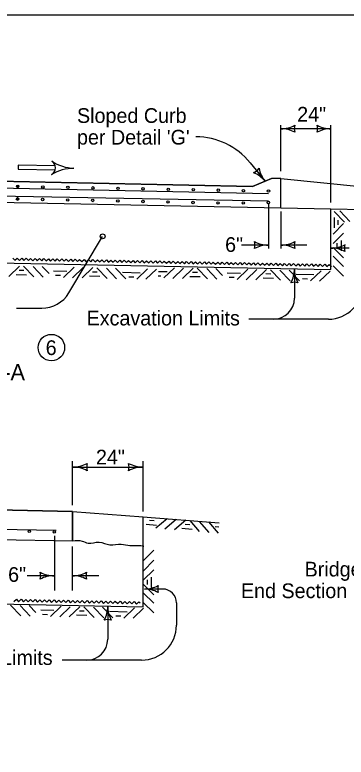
# Model space of a CAD drawing. Extents: x 8925 to 81668, y 4369 to 11918.
# Drawn here: x 17971 to 18420, y 8936 to 9944 of the extents above; entities that cross this region are included whole.
import ezdxf

# ---------------------------------------------------------------- set-up
doc = ezdxf.new("R2010")
doc.units = 0
for name, color, linetype in [('dsnShtPlotShapeBatchPrint', 7, 'Continuous'), ('dsnStdBorder', 7, 'Continuous'), ('SheetBorder', 7, 'Continuous')]:
    doc.layers.add(name, color=color, linetype=linetype)

msp = doc.modelspace()

# ---------------------------------------------------------------- linework, layer by layer
at = {"layer": 'dsnShtPlotShapeBatchPrint'}
msp.add_line((18314.8, 9691.1), (17583.2, 9704.6), dxfattribs=at)
at = {"layer": 'dsnStdBorder'}
for p, q in [((18331.8, 9731.9), (18331.8, 9794)), ((18399.8, 9689), (18399.8, 9794)), ((18399.8, 9789.3), (18331.8, 9789.3)), ((18290.1, 9743.1), (18310.3, 9717.9)), ((18025.3, 9733.3), (18025.3, 9733.3)), ((18025.4, 9739.1), (18025.4, 9739.1)), ((18293.5, 9710.9), (17583.3, 9725.2)), ((17583.3, 9725.2), (18293.5, 9710.9)), ((18319, 9721.5), (18293.5, 9710.9)), ((18293.5, 9710.9), (18319, 9721.5)), ((18331.8, 9721.5), (18319, 9721.5)), ((18331.8, 9721.5), (18319, 9721.5)), ((18331.8, 9681.8), (18331.8, 9721.5)), ((18331.8, 9681.8), (18331.8, 9721.5)), ((18331.8, 9721.5), (18444.1, 9710.3)), ((17583.3, 9716.2), (18315, 9701.5)), ((17582.7, 9696.8), (18331.8, 9681.8)), ((17583.8, 9696.8), (18331.8, 9681.8)), ((18314.8, 9687.3), (18314.8, 9626.6)), ((18331.8, 9681.8), (18399.8, 9680.4)), ((18399.8, 9598), (18399.8, 9680.4)), ((18399.8, 9680.4), (18577.7, 9676.8)), ((18331.8, 9677.1), (18331.8, 9626.6)), ((18404.3, 9676.9), (18418.2, 9662.5)), ((18411.6, 9677.9), (18425.4, 9663.4)), ((18402.9, 9646.3), (18417, 9660.5)), ((18043.9, 9566.2), (18089.9, 9643.1)), ((18402.7, 9633.3), (18416.8, 9647.4)), ((18314.8, 9631.3), (18278.2, 9631.3)), ((18367, 9631.3), (18331.8, 9631.3)), ((18424.6, 9627.2), (18399.8, 9627.2)), ((18402.7, 9627.9), (18416.8, 9613.8)), ((17583.3, 9614.4), (18399.8, 9598)), ((18402.7, 9616.3), (18416.8, 9602.2)), ((17977.1, 9602.6), (17962.7, 9588.7)), ((17982.5, 9602.5), (17996.4, 9588)), ((17995.5, 9602), (18009.4, 9587.6)), ((18008, 9602), (18017.1, 9592.5)), ((18051.2, 9601.1), (18036.8, 9587.2)), ((18063.6, 9600.6), (18049.2, 9586.8)), ((18076.6, 9600.6), (18062.2, 9586.7)), ((18082, 9600.5), (18095.9, 9586)), ((18095, 9600), (18108.9, 9585.6)), ((18107.5, 9600), (18121.4, 9585.5)), ((18187.2, 9600.4), (18172.8, 9586.6)), ((18199.7, 9600), (18185.3, 9586.1)), ((18212.7, 9599.9), (18198.3, 9586.1)), ((18218.1, 9599.8), (18232, 9585.4)), ((18231.1, 9599.3), (18245, 9584.9)), ((18243.6, 9599.3), (18252.7, 9589.8)), ((18402.7, 9603.3), (18416.8, 9589.1)), ((18150.7, 9599.1), (18136.3, 9585.2)), ((18163.2, 9598.6), (18148.7, 9584.8)), ((18286.8, 9598.5), (18272.4, 9584.6)), ((18299.2, 9598), (18284.8, 9584.1)), ((18312.2, 9597.9), (18297.8, 9584.1)), ((18317.6, 9597.8), (18331.5, 9583.4)), ((18330.6, 9597.3), (18344.5, 9582.9)), ((18343.1, 9597.3), (18357, 9582.9)), ((18350.2, 9599), (18350.2, 9559)), ((18386.3, 9596.5), (18371.9, 9582.6)), ((18398.8, 9596), (18384.3, 9582.1)), ((17973.1, 9545.5), (18007.4, 9545.5)), ((18396.2, 9530.6), (18288.4, 9530.6)), ((18049.1, 9278.1), (18049.1, 9337.8)), ((18145.1, 9269.5), (18145.1, 9337.8)), ((18049.1, 9329.8), (18145.1, 9329.8)), ((18049.1, 9269.5), (17676.1, 9277)), ((17676.1, 9277), (18049.1, 9269.5)), ((18049.1, 9229.5), (18049.1, 9269.5)), ((18049.1, 9269.5), (18049.1, 9229.5)), ((18049.1, 9269.5), (18145.1, 9262.1)), ((18144.4, 9262.1), (18247.9, 9254.1)), ((18145.1, 9139.8), (18145.1, 9262.1)), ((18177.3, 9259.6), (18162.1, 9246.6)), ((18189.7, 9258.4), (18174.5, 9245.4)), ((18202.7, 9257.6), (18187.5, 9244.6)), ((18208.1, 9257.2), (18221.1, 9242)), ((18027, 9243.5), (17725.6, 9249.6)), ((18221.1, 9256), (18234.1, 9240.8)), ((18233.5, 9255.3), (18246.5, 9240.1)), ((17676.1, 9237), (18049.1, 9229.5)), ((17676.1, 9237), (18049.1, 9229.5)), ((18025.1, 9162), (18025.1, 9236.4)), ((18049.1, 9162), (18049.1, 9221.7)), ((18145.3, 9202.7), (18159.4, 9216.9)), ((18145.3, 9188.9), (18159.4, 9203.1)), ((18145.1, 9175.9), (18159.2, 9190.1)), ((18024.1, 9182.1), (17987.5, 9182.1)), ((18084.8, 9182.1), (18049.1, 9182.1)), ((18145.1, 9170.5), (18159.2, 9156.4)), ((18145.1, 9158.9), (18159.2, 9144.8)), ((18171.2, 9164.1), (18146.5, 9164.1)), ((17676.1, 9149.2), (18145, 9139.8)), ((18145.1, 9145.9), (18159.2, 9131.7)), ((17964.9, 9142), (17978.7, 9127.5)), ((17977.9, 9141.5), (17991.7, 9127.1)), ((17990.3, 9141.5), (17999.4, 9132)), ((18033.5, 9140.6), (18019.1, 9126.7)), ((18046, 9140.1), (18031.6, 9126.3)), ((18059, 9140.1), (18044.6, 9126.2)), ((18064.4, 9140), (18078.3, 9125.5)), ((18077.4, 9139.5), (18091.3, 9125.1)), ((18089.9, 9139.5), (18103.7, 9125)), ((18096.8, 9140.8), (18096.8, 9095.9)), ((18133.1, 9138.6), (18118.6, 9124.7)), ((18145.5, 9138.1), (18131.1, 9124.3)), ((18190.1, 9145.2), (18190.1, 9114.8)), ((18142.8, 9067.6), (18035.1, 9067.6))]:
    msp.add_line(p, q, dxfattribs=at)
for points in [[(18025.4, 9738.9), (17975.4, 9739.9), (17975.3, 9734.3), (18025.3, 9733.3)], [(17973.2, 9710.8), (17973.5, 9711.3), (17973.8, 9712.2), (17974.7, 9712.3), (17975.4, 9712.2), (17976.1, 9711.6), (17976, 9710.8), (17975.9, 9709.9), (17975.2, 9709.5), (17974.4, 9709.5), (17973.5, 9710), (17973.4, 9710.7), (17973.7, 9711.5), (17974.3, 9712.2), (17975.1, 9712.2), (17975.7, 9711.6), (17975.8, 9710.8), (17975.6, 9709.9), (17975.1, 9709.8), (17974.5, 9709.7), (17973.8, 9710.1), (17973.8, 9710.7), (17974, 9711.5), (17974.4, 9712), (17975.1, 9711.7), (17975.5, 9711.1), (17975.5, 9710.4), (17975.1, 9710.2), (17974.7, 9710), (17974.1, 9710.4), (17974, 9710.9), (17974.3, 9711.4), (17974.8, 9711.4), (17975.2, 9711.1), (17975.3, 9710.6), (17975.1, 9710.4), (17974.8, 9710.3), (17974.4, 9710.5), (17974.3, 9710.9), (17974.5, 9711.2), (17974.8, 9711.2), (17975, 9710.9), (17974.9, 9710.6), (17974.7, 9710.6), (17974.6, 9710.9)], [(17975.9, 9693.8), (17975.7, 9694.4), (17975.4, 9695.2), (17974.5, 9695.4), (17973.7, 9695.3), (17973, 9694.7), (17973.1, 9693.9), (17973.2, 9693), (17973.9, 9692.6), (17974.6, 9692.5), (17975.6, 9693), (17975.7, 9693.7), (17975.5, 9694.5), (17974.9, 9695.3), (17974.1, 9695.2), (17973.4, 9694.7), (17973.3, 9693.9), (17973.5, 9693), (17974, 9692.9), (17974.6, 9692.7), (17975.3, 9693.1), (17975.3, 9693.8), (17975.2, 9694.5), (17974.8, 9695), (17974, 9694.7), (17973.6, 9694.2), (17973.6, 9693.5), (17974, 9693.3), (17974.4, 9693), (17975, 9693.4), (17975.1, 9693.9), (17974.9, 9694.4), (17974.3, 9694.5), (17974, 9694.2), (17973.8, 9693.7), (17974, 9693.5), (17974.3, 9693.3), (17974.8, 9693.6), (17974.8, 9693.9), (17974.6, 9694.3), (17974.3, 9694.2), (17974.2, 9694), (17974.2, 9693.6), (17974.4, 9693.6), (17974.5, 9693.9)], [(18404.5, 9654.8), (18404.5, 9668.9)], [(18409.6, 9658.6), (18409.6, 9665.1)], [(18408.2, 9627.3), (18408.2, 9633.9)], [(18414, 9623.5), (18414, 9637.7)], [(17968, 9613.7), (17970.9, 9610.6), (17974, 9613.6), (17977, 9610.5), (17980, 9613.5), (17983, 9610.4), (17986.1, 9613.3), (17989.1, 9610.3), (17992.1, 9613.2), (17995.1, 9610.1), (17998.2, 9613.1), (17999.7, 9611.6)], [(17999.7, 9611.6), (18001.2, 9610), (18004.2, 9613), (18007.2, 9609.9), (18010.3, 9612.9), (18013.3, 9609.8), (18016.3, 9612.7), (18019.3, 9609.6), (18022.4, 9612.6), (18025.4, 9609.5), (18028.4, 9612.5), (18031.4, 9609.4), (18034.5, 9612.4), (18037.5, 9609.3), (18040.5, 9612.2), (18043.5, 9609.2), (18046.6, 9612.1), (18049.5, 9609), (18052.6, 9612), (18055.6, 9608.9), (18058.7, 9611.9), (18061.6, 9608.8), (18064.7, 9611.8), (18067.7, 9608.7), (18070.8, 9611.6), (18072.3, 9610.1)], [(18072.3, 9610.1), (18073.7, 9608.6), (18076.8, 9611.5), (18079.8, 9608.4), (18082.9, 9611.4), (18085.8, 9608.3), (18088.9, 9611.3), (18091.9, 9608.2), (18095, 9611.2), (18097.9, 9608.1), (18101, 9611), (18104, 9607.9), (18107.1, 9610.9), (18110, 9607.8), (18113.1, 9610.8), (18116.1, 9607.7), (18119.2, 9610.7), (18122.1, 9607.6), (18125.2, 9610.5), (18128.2, 9607.5), (18131.3, 9610.4), (18134.2, 9607.3), (18137.3, 9610.3), (18140.3, 9607.2), (18143.4, 9610.2), (18144.8, 9608.6)], [(18144.8, 9608.6), (18146.3, 9607.1), (18149.4, 9610.1), (18152.4, 9607), (18155.5, 9609.9), (18158.4, 9606.9), (18161.5, 9609.8), (18164.5, 9606.7), (18167.6, 9609.7), (18170.5, 9606.6), (18173.6, 9609.6), (18176.6, 9606.5), (18179.7, 9609.5), (18182.6, 9606.4), (18185.7, 9609.3), (18188.7, 9606.2), (18191.8, 9609.2), (18194.7, 9606.1), (18197.8, 9609.1), (18200.8, 9606), (18203.9, 9609), (18206.8, 9605.9), (18209.9, 9608.8), (18212.9, 9605.8), (18215.9, 9608.7), (18217.4, 9607.2)], [(18217.4, 9607.2), (18218.9, 9605.6), (18222, 9608.6), (18225, 9605.5), (18228, 9608.5), (18231, 9605.4), (18234.1, 9608.4), (18237.1, 9605.3), (18240.1, 9608.2), (18243.1, 9605.2), (18246.2, 9608.1), (18249.2, 9605), (18252.2, 9608), (18255.2, 9604.9), (18258.3, 9607.9), (18261.3, 9604.8), (18264.3, 9607.8), (18267.3, 9604.7), (18270.4, 9607.6), (18273.4, 9604.5), (18276.4, 9607.5), (18279.4, 9604.4), (18282.5, 9607.4), (18285.4, 9604.3), (18288.5, 9607.3), (18290, 9605.7)], [(18290, 9605.7), (18291.5, 9604.2), (18294.6, 9607.1), (18297.5, 9604.1), (18300.6, 9607), (18303.6, 9603.9), (18306.7, 9606.9), (18309.6, 9603.8), (18312.7, 9606.8), (18315.7, 9603.7), (18318.8, 9606.7), (18321.7, 9603.6), (18324.8, 9606.5), (18327.8, 9603.5), (18330.9, 9606.4), (18333.8, 9603.3), (18336.9, 9606.3), (18339.9, 9603.2), (18343, 9606.2), (18345.9, 9603.1), (18349, 9606.1), (18352, 9603), (18355.1, 9605.9), (18358, 9602.8), (18361.1, 9605.8), (18362.6, 9604.3)], [(18362.6, 9604.3), (18364.1, 9602.7), (18367.2, 9605.7), (18370.1, 9602.6), (18373.2, 9605.6), (18376.2, 9602.5), (18379.3, 9605.4), (18382.2, 9602.4), (18385.3, 9605.3), (18388.3, 9602.2), (18391.4, 9605.2), (18394.3, 9602.1), (18397.4, 9605.1), (18400.4, 9602), (18400.6, 9602.2)], [(17972.5, 9591.3), (17986.7, 9591)], [(17976.4, 9597.1), (17983, 9597)], [(18023.4, 9596.2), (18041.5, 9595.8)], [(18026.1, 9590.3), (18032.6, 9590.2)], [(18072, 9589.3), (18086.2, 9589)], [(18076, 9595.1), (18082.5, 9595)], [(18117, 9594.3), (18141, 9593.8)], [(18165.4, 9589.6), (18168.7, 9589.5)], [(18165.5, 9595.4), (18177.6, 9595.2)], [(18212, 9594.5), (18218.6, 9594.3)], [(18259, 9593.5), (18277.1, 9593.2)], [(18311.6, 9592.5), (18318.1, 9592.3)], [(18352.6, 9591.7), (18376.6, 9591.2)], [(18125.6, 9588.3), (18132.1, 9588.2)], [(18208.1, 9588.7), (18222.3, 9588.4)], [(18261.7, 9587.7), (18268.2, 9587.5)], [(18307.6, 9586.7), (18321.8, 9586.4)], [(18361.2, 9585.7), (18367.7, 9585.5)], [(18153.3, 9257.6), (18159.9, 9257.1)], [(18149.1, 9252), (18163.2, 9250.9)], [(18197.5, 9246.6), (18211.6, 9245.6)], [(18201.7, 9252.2), (18208.2, 9251.7)], [(18242.6, 9249.1), (18247.5, 9248.7)], [(18150.6, 9170), (18150.6, 9176.5)], [(18156.4, 9166.1), (18156.4, 9180.3)], [(17969.5, 9147.1), (17972.8, 9150.2), (17975.9, 9146.9), (17979.1, 9150.1), (17982.3, 9146.8), (17985.5, 9149.9), (17987.1, 9148.3)], [(17987.1, 9148.3), (17988.7, 9146.7), (17991.9, 9149.8), (17995.1, 9146.5), (17998.3, 9149.7), (18001.5, 9146.4), (18004.7, 9149.5), (18007.9, 9146.3), (18011.1, 9149.4), (18014.3, 9146.2), (18017.5, 9149.3), (18020.7, 9146), (18023.9, 9149.2), (18027.1, 9145.9), (18030.3, 9149), (18033.5, 9145.8), (18036.7, 9148.9), (18039.9, 9145.6), (18043.1, 9148.8), (18046.3, 9145.5), (18049.5, 9148.6), (18052.7, 9145.4), (18055.9, 9148.5), (18059.1, 9145.3), (18062.3, 9148.4), (18063.9, 9146.8)], [(18063.9, 9146.8), (18065.5, 9145.1), (18068.7, 9148.3), (18071.9, 9145), (18075.1, 9148.1), (18078.3, 9144.9), (18081.5, 9148), (18084.7, 9144.7), (18087.9, 9147.9), (18091.1, 9144.6), (18094.3, 9147.7), (18097.5, 9144.5), (18100.7, 9147.6), (18103.9, 9144.4), (18107.1, 9147.5), (18110.3, 9144.2), (18113.5, 9147.4), (18116.7, 9144.1), (18119.9, 9147.2), (18123.1, 9144), (18126.3, 9147.1), (18129.5, 9143.8), (18132.7, 9147), (18135.9, 9143.7), (18139.1, 9146.8), (18140.7, 9145.2)], [(18005.8, 9135.7), (18023.8, 9135.3)], [(18008.4, 9129.8), (18015, 9129.7)], [(18054.4, 9128.8), (18068.6, 9128.5)], [(18058.3, 9134.6), (18064.9, 9134.5)], [(18099.3, 9133.8), (18123.4, 9133.3)], [(18108, 9127.8), (18114.5, 9127.7)]]:
    msp.add_lwpolyline(points, dxfattribs=at)
for centre, radius in [((17974.7, 9710.9), 1.65), ((17974.7, 9710.9), 1.65), ((18008.7, 9710.2), 1.65), ((18042.7, 9709.6), 1.65), ((18076.8, 9709), 1.65), ((18110.8, 9708.4), 1.65), ((18144.8, 9707.7), 1.65), ((18178.9, 9707.1), 1.65), ((18212.9, 9706.5), 1.65), ((18246.9, 9705.9), 1.65), ((18281, 9705.2), 1.65), ((18315, 9704.6), 1.65), ((17974.4, 9693.9), 1.65), ((17974.4, 9693.9), 1.65), ((18008.4, 9693.2), 1.65), ((18042.5, 9692.6), 1.65), ((18076.5, 9691.9), 1.65), ((18110.5, 9691.2), 1.65), ((18144.6, 9690.5), 1.65), ((18178.6, 9689.8), 1.65), ((18212.6, 9689.1), 1.65), ((18246.6, 9688.5), 1.65), ((18280.7, 9688.5), 1.65), ((18314.7, 9689.1), 1.65), ((18089.9, 9643.1), 3.31), ((18020.3, 9492), 18), ((17990.3, 9242.6), 1.65), ((18024.3, 9241.6), 1.65)]:
    msp.add_circle(centre, radius, dxfattribs=at)
for centre, radius, start, end in [((18331.8, 9829.5), 40.2, 270, 298.0725), ((18331.8, 9829.5), 40.2, 270, 298.0725), ((18365.5, 9789.3), 15.5, 162.2666, 197.7334), ((18365.5, 9789.3), 15.5, 162.2666, 197.7334), ((18366.2, 9789.3), 15.5, 342.2666, 17.7334), ((18399.9, 9829.5), 40.2, 241.9275, 270), ((18366.2, 9789.3), 15.5, 342.2666, 17.7334), ((18399.9, 9829.5), 40.2, 241.9275, 270), ((18331.8, 9749.1), 40.2, 61.9275, 90), ((18331.8, 9749.1), 40.2, 61.9275, 90), ((18399.9, 9749.1), 40.2, 90, 118.0725), ((18399.9, 9749.1), 40.2, 90, 118.0725), ((18216.4, 9683.8), 94.5, 38.8378, 90), ((18015.1, 9736.3), 10.7, 300.5647, 57.1354), ((18054, 9796.5), 61, 237.1358, 267.1658), ((18054, 9796.5), 61, 237.1363, 267.1658), ((18015.1, 9736.3), 10.7, 14.2596, 57.1327), ((18051.5, 9674.6), 61, 90.5343, 120.5643), ((18051.5, 9674.6), 61, 90.5343, 120.5638), ((18015.1, 9736.3), 10.7, 300.5675, 343.43), ((18289.2, 9744.1), 15.5, 291.1048, 326.5715), ((18341.6, 9743.1), 40.2, 190.7656, 218.8381), ((18279, 9692.7), 40.2, 38.8381, 66.9106), ((18281.1, 9631.3), 15.5, 342.2666, 17.7334), ((18314.8, 9671.5), 40.2, 241.9275, 270), ((18314.8, 9591.1), 40.2, 90, 118.0725), ((18331.8, 9671.5), 40.2, 270, 298.0725), ((18331.8, 9591.1), 40.2, 61.9275, 90), ((18365.5, 9631.3), 15.5, 162.2666, 197.7334), ((18399.9, 9667.3), 40.2, 270, 298.0725), ((18433.5, 9627.2), 15.5, 162.2666, 197.7334), ((18399.9, 9587), 40.2, 61.9275, 90), ((18310, 9599), 40.2, 331.9275, 360), ((18390.3, 9599), 40.2, 180, 208.0725), ((18350.2, 9565.3), 15.5, 72.2666, 107.7334), ((18396.2, 9577.9), 47.3, 270, 360), ((18007.4, 9588), 42.5, 270, 329.1249), ((18321.8, 9559), 28.4, 270, 360), ((18049.1, 9372.3), 42.5, 270, 298.0725), ((18049.1, 9287.3), 42.5, 61.9275, 90), ((18084.7, 9329.8), 16.4, 162.2666, 197.7334), ((18109.4, 9329.8), 16.4, 342.2666, 17.7333), ((18145.1, 9372.3), 42.5, 241.9275, 270), ((18109.4, 9329.8), 16.4, 342.2666, 17.7333), ((18145.1, 9372.3), 42.5, 241.9275, 270), ((18145.1, 9287.3), 42.5, 90, 118.0725), ((18145.1, 9287.3), 42.5, 90, 118.0725), ((17990.4, 9182.1), 15.5, 342.2666, 17.7334), ((18024.1, 9222.3), 40.2, 241.9275, 270), ((17990.4, 9182.1), 15.5, 342.2666, 17.7334), ((18024.1, 9222.3), 40.2, 241.9275, 270), ((18049.1, 9222.3), 40.2, 270, 298.0725), ((18082.7, 9182.1), 15.5, 162.2666, 197.7334), ((18024.1, 9142), 40.2, 90, 118.0725), ((18024.1, 9142), 40.2, 90, 118.0725), ((18049.1, 9142), 40.2, 61.9275, 90), ((18146.5, 9204.3), 40.2, 270, 298.0725), ((18146.5, 9204.3), 40.2, 270, 298.0725), ((18180.2, 9164.1), 15.5, 162.2666, 197.7334), ((18180.2, 9164.1), 15.5, 162.2666, 197.7334), ((18146.5, 9123.9), 40.2, 61.9275, 90), ((18146.5, 9123.9), 40.2, 61.9275, 90), ((18171.2, 9145.2), 18.9, 0, 90), ((18056.6, 9140.8), 40.2, 331.9275, 360), ((18137, 9140.8), 40.2, 180, 208.0725), ((18096.8, 9107.1), 15.5, 72.2666, 107.7334), ((18142.8, 9114.8), 47.3, 270, 360), ((18068.4, 9095.9), 28.4, 270, 360)]:
    msp.add_arc(centre, radius, start, end, dxfattribs=at)
msp.add_spline([(18049.1, 9229.5), (18062, 9229.3), (18070.1, 9226.4), (18085, 9227.8), (18099.8, 9224), (18115.1, 9225), (18127, 9223.1), (18141.9, 9223.1), (18145.7, 9222.1)], degree=3, dxfattribs=at)
at = {"layer": 'SheetBorder'}
msp.add_lwpolyline([(17332.5, 9944), (20467.5, 9944), (20467.5, 7924), (17332.5, 7924)], close=True, dxfattribs=at)

# ---------------------------------------------------------------- texts
at = {"layer": 'dsnShtPlotShapeBatchPrint'}
for s, height, p in [('Sloped Curb', 20, (18055.1, 9797.2)), ('24"', 20, (18353.9, 9799)), ("per Detail 'G'", 20, (18055.1, 9767.8)), ('6"', 20, (18256.1, 9622)), ('Excavation Limits', 20, (18068.1, 9522.1)), ('6', 20, (18012.6, 9481.9)), ('SECTION A-A', 22, (17796.5, 9447.7)), ('24"', 20, (18080.8, 9333.3)), ('6"', 20, (17961.6, 9173.8)), ('Excavation Limits', 20, (17813.9, 9061))]:
    msp.add_text(s, height=height, dxfattribs=at).set_placement(p)
at = {"layer": 'dsnStdBorder'}
for s, p in [('Bridge Rail', (18364, 9181.1)), ('End Section (typ.)', (18277.6, 9151.7))]:
    msp.add_text(s, height=20, dxfattribs=at).set_placement(p)

doc.saveas('drawing.dxf')
